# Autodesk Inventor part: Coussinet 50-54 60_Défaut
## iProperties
Shininess: 64.0
Length Units: 11269
Angle Units: 11279
Time Units: 11290
Mass Units: 11283
Length Display Precision: 3
Angle Display Precision: 2
Compacted: True
Part Number: Coussinet 50-54 60_Défaut
Document SubType Name: Modeling
Created: 2006-11
Material: Par défaut
Designer: profs_sti
Density: 0.0
Volumn: 0.0
Area: 0.0
PropertySet Name: Model Information
Control State: 0
Master: False
Checked Out: False
Author: profs_sti
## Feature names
1. Base1
